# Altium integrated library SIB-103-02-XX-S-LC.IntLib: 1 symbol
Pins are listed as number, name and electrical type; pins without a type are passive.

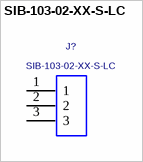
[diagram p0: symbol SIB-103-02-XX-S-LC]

## SIB-103-02-XX-S-LC
designator J?
0.100"  SINGLE INTERFACE BEAM ASSEMBLY.; MANUFACTURER: SAMTEC
footprint SIB-103-02-XX-S-LC
pins: 1, 2, 3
